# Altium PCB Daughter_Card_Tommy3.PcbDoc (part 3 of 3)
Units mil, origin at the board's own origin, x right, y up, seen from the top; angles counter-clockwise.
Board outline 2032.68 x 3237.01 mil, 8 copper layers (Top Layer, GND, AUX Routing (LVDS), 2.5V, AUX Route Vert, AUX Route Horz, GND (Plane2), Bottom Layer), stack 61.2 mil thick; 218 components, 194 nets, 1097 pads, 500 vias.
Unrouted connection lines stored in the file: 161.
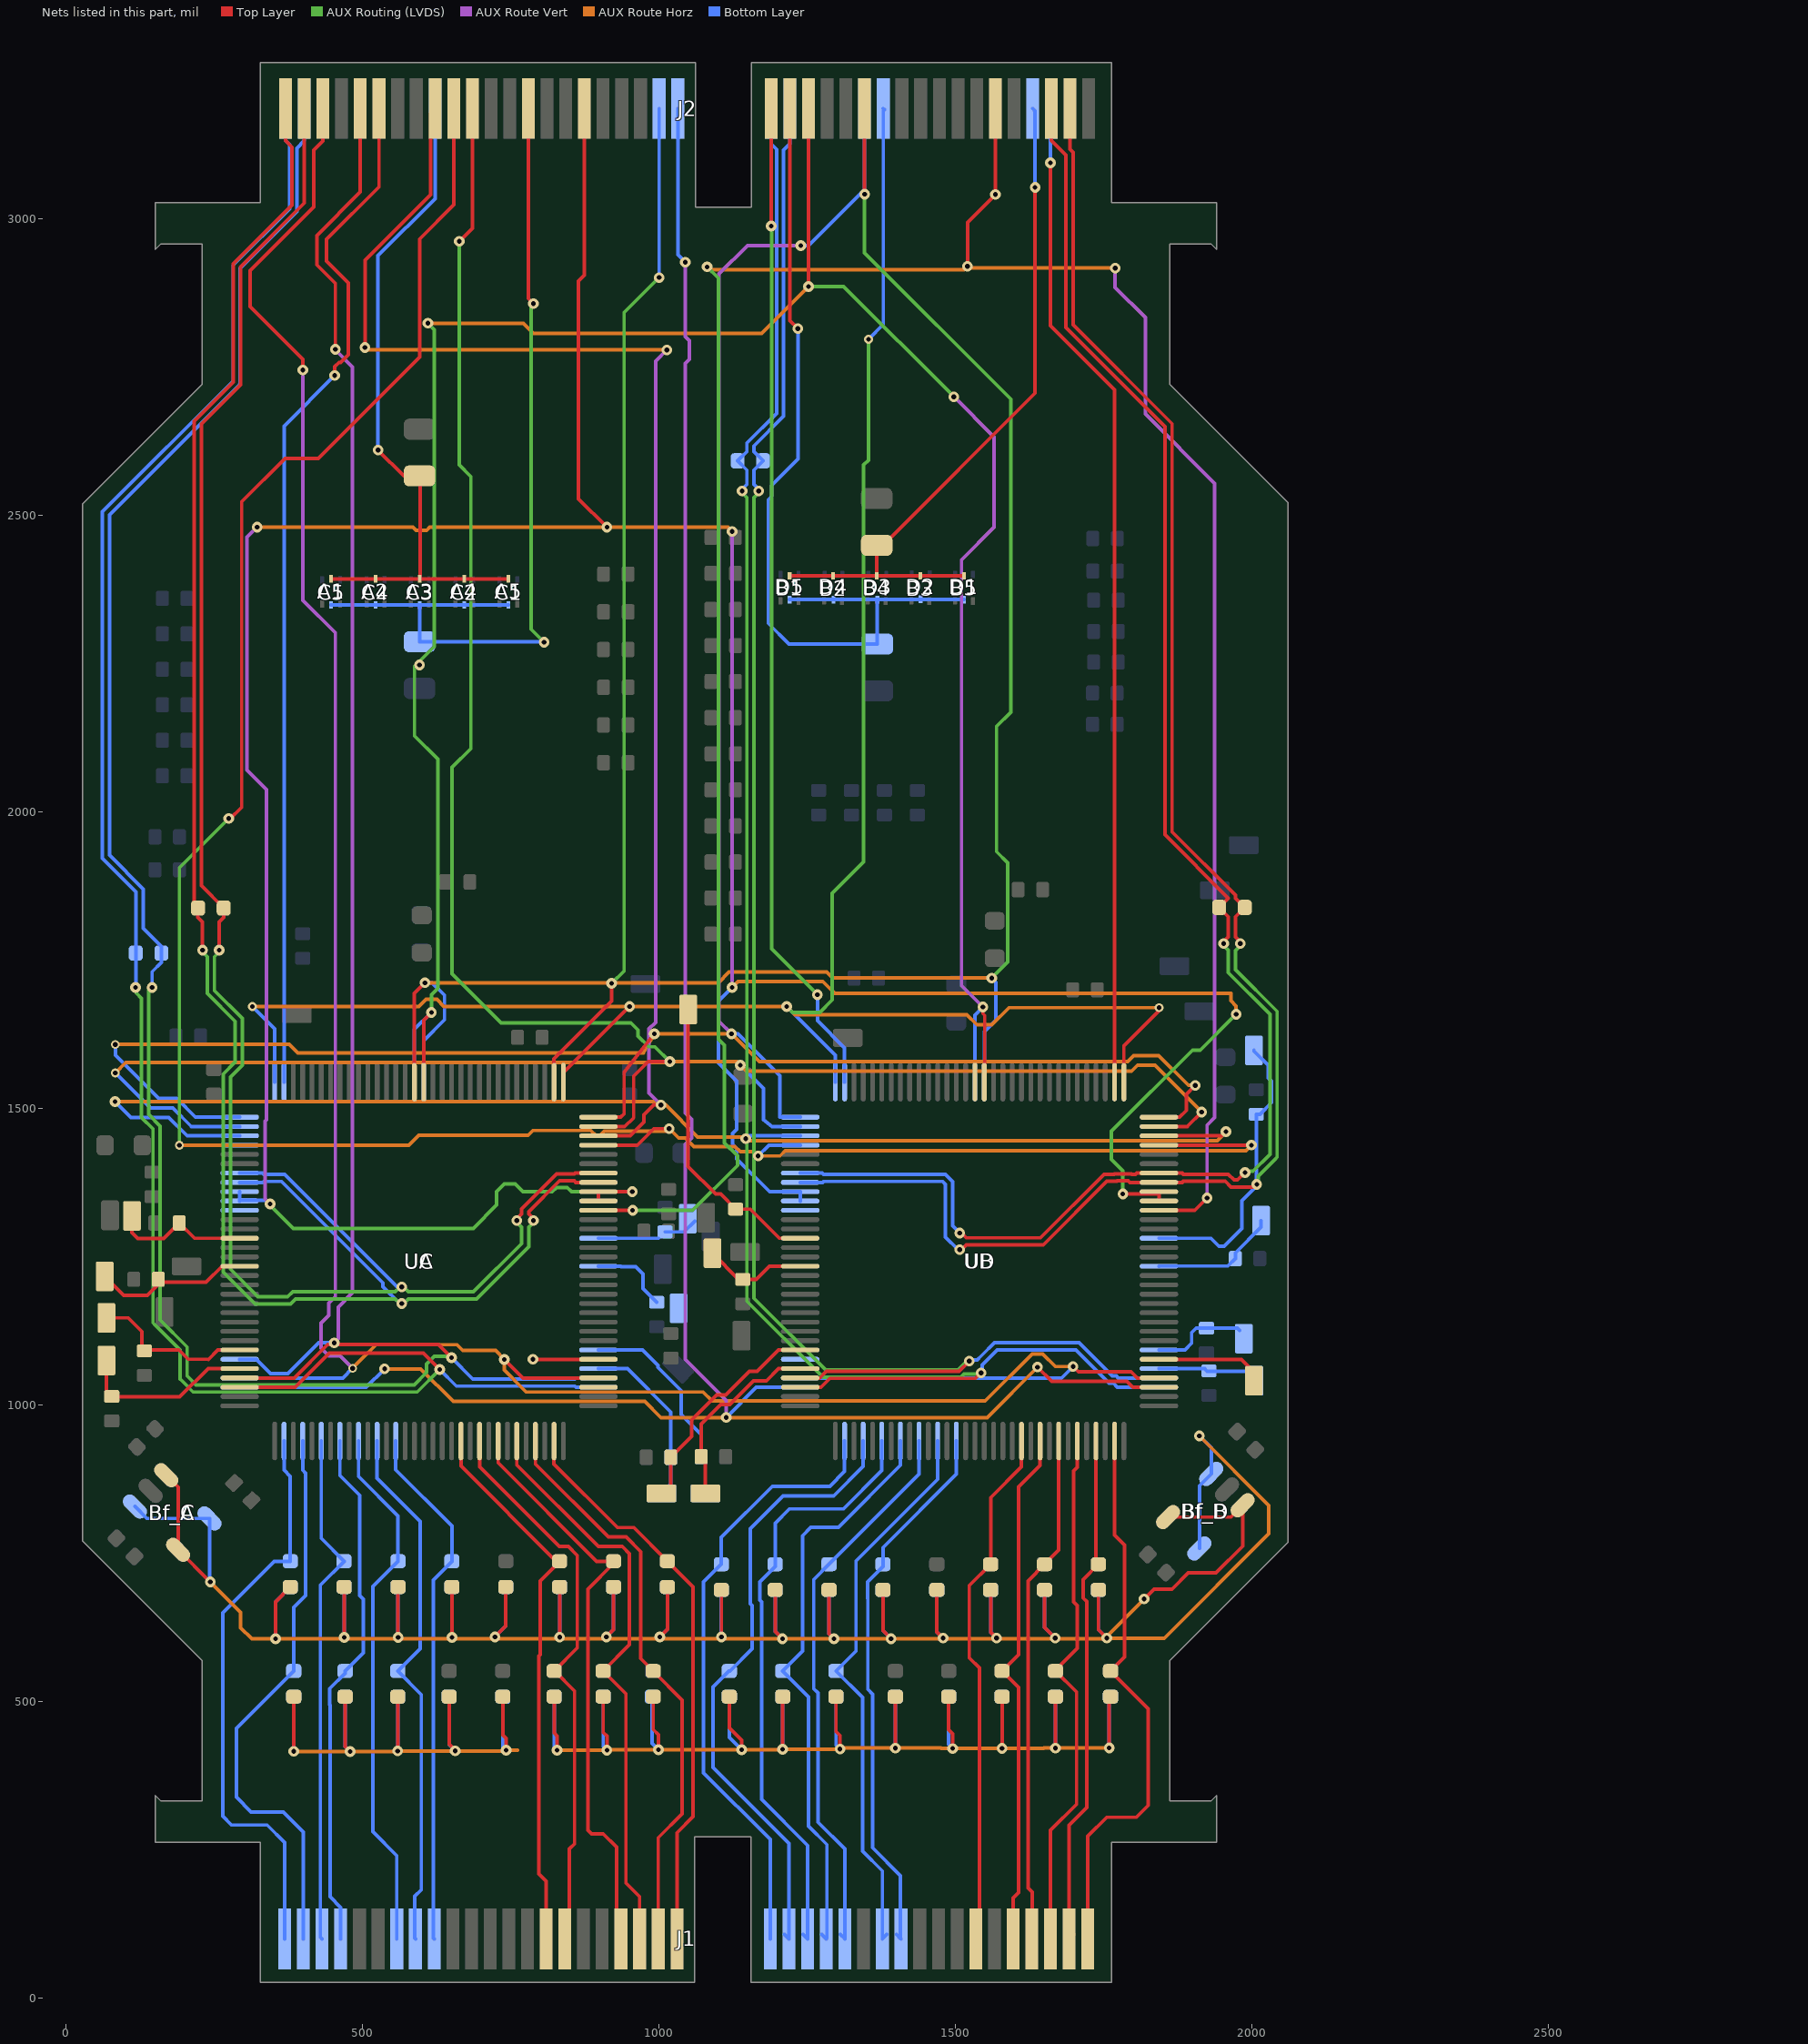
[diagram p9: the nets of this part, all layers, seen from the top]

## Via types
v1: diameter 18, hole 8, Top Layer to Bottom Layer, 106 vias
v2: diameter 18, hole 8, Top Layer to AUX Route Horz, 56 vias
v3: diameter 15, hole 8, Top Layer to Bottom Layer, 53 vias
v4: diameter 18, hole 8, AUX Route Vert to Bottom Layer, 42 vias
v5: diameter 18, hole 8, AUX Route Horz to Bottom Layer, 40 vias
v6: diameter 18, hole 8, Top Layer to AUX Route Vert, 34 vias
v7: diameter 18, hole 8, Top Layer to GND, 33 vias
v8: diameter 18, hole 8, GND (Plane2) to Bottom Layer, 27 vias
v9: diameter 18, hole 8, AUX Routing (LVDS) to Bottom Layer, 23 vias
v10: diameter 18, hole 8, Top Layer to AUX Routing (LVDS), 22 vias
v11: diameter 15, hole 8, Top Layer to 2.5V, 13 vias
v12: diameter 18, hole 8, Top Layer to 2.5V, 13 vias
v13: diameter 15, hole 8, Top Layer to GND, 10 vias
v14: diameter 18, hole 8, 2.5V to Bottom Layer, 8 vias
v15: diameter 15, hole 8, GND (Plane2) to Bottom Layer, 4 vias
v16: diameter 15, hole 8, Top Layer to AUX Route Horz, 4 vias
v17: diameter 18, hole 8, AUX Route Vert to AUX Route Horz, 4 vias
v18: diameter 15, hole 8, 2.5V to Bottom Layer, 2 vias
v19: diameter 18, hole 8, AUX Routing (LVDS) to AUX Route Vert, 2 vias
v20: diameter 15 (per signal layer), hole 8, Top Layer to GND, 1 vias
v21: diameter 15, hole 8, AUX Routing (LVDS) to Bottom Layer, 1 vias
v22: diameter 15, hole 8, Top Layer to AUX Route Vert, 1 vias
v23: diameter 8, hole 8, Top Layer to AUX Route Horz, 1 vias

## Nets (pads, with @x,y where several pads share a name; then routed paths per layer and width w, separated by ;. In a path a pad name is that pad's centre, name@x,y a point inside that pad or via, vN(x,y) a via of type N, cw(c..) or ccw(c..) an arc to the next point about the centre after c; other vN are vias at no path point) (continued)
RFin_10_C: J1.18 R10C.2 UC.19 | length 892.4
  Bottom Layer w6: UC.19@555.87,939.47 555.87,890.87 650.53,796.21 R10C.2@650.53,736.65 619,705.13 619,101.55 J1.18@620.55,100
RFin_10_D: J1.60 R10D.2 UD.19 | length 934.3
  Bottom Layer w6: J1.60@1400.28,107.67 J1.60@1407,100.95 ; J1.60@1407.95,100 J1.60@1407,100.95 ; UD.19@1501.18,939.47 1501.18,883.55 1377.39,759.77 R10D.2@1377.39,731.65 1377.39,727.88 1351.6,702.08 1351.6,674.21 1352,673.81 1352,520.63 1360,512.63 1360,253.63 1407,206.63 J1.60@1407,100.95
RFin_11_A: J1.29 R11A.2 UA.21 | length 925.6
  Top Layer w6: UA.21@665.77,939.47 665.77,897.23 R11A.2@826.35,736.65 ; J1.29@809.53,100 809.53,197.47 797.2,209.8 797.2,577.2 799.18,579.18 799.18,703.59 R11A.2@832.24,736.65
RFin_11_B: J1.67 R11B.2 UB.21 | length 896.4
  Top Layer w6: J1.67@1526.27,107.67 J1.67@1533.94,100 1540,106.06 1540,557 1523,574 1523,695.54 R11B.2@1559.11,731.65 1559.11,844.11 1611.08,896.08 UB.21@1611.08,939.47
RFin_11_C: J1.16 R11C.2 UC.21 | length 906.6
  Bottom Layer w6: UC.21@524.47,939.47 524.47,876.53 597,804 597,589.44 R11C.2@559.21,551.65 599,511.87 599,183 588,172 588,101.05 J1.16@589.05,100
RFin_11_D: J1.58 R11D.2 UD.21 | length 953.5
  Bottom Layer w6: J1.58@1384,107.54 J1.58@1376.46,100 1376.46,214.54 1343,248 1343,507 R11D.2@1298.35,551.65 1332,585.31 1332,737 1469.78,874.78 UD.21@1469.78,939.47
RFin_12_A: J1.31 R12A.2 UA.23 | length 954.1
  Top Layer w6: UA.23@697.17,939.47 697.17,896.17 831.87,761.46 846.96,761.46 862,746.43 862,590.66 R12A.2@822.99,551.65 823.69,551.65 857.35,518 857.35,260.09 848.69,251.43 848.69,107.67 J1.31@841.02,100
RFin_12_B: J1.71 R12B.2 UB.23 | length 891.4
  Top Layer w6: J1.71@1604.14,107.21 1596.93,100 1596.93,168.93 1606,178 1606,524 R12B.2@1578.35,551.65 1606,579.31 1606,862 1642.48,898.48 UB.23@1642.48,939.47
RFin_12_C: J1.14 R12C.2 UC.23 | length 901.5
  Bottom Layer w6: UC.23@493.07,939.47 493.07,879.93 559.67,813.33 R12C.2@559.67,736.65 517,693.98 517,281 557.56,240.44 J1.14@557.56,100
RFin_12_D: J1.54 R12D.2 UD.23 | length 945.1
  Bottom Layer w6: J1.54@1305.79,107.67 J1.54@1313,100.46 ; J1.54@1313.46,100 J1.54@1313,100.46 ; UD.23@1438.38,939.47 1438.38,883.5 R12D.2@1286.53,731.65 1260.74,705.86 1260.74,521.89 1268,514.63 1268,296.63 1313,251.63 J1.54@1313,100.46
RFin_13_A: J1.37 R13A.2 UA.25 | length 978.8
  Top Layer w6: UA.25@728.57,939.47 728.57,902.49 894.4,736.65 R13A.2@923.1,736.65 923.1,732.88 879.87,689.65 879.87,283.13 886,277 905.74,277 928,254.74 J1.37@928,107.51
RFin_13_B: J1.73 R13B.2 UB.25 | length 861.3
  Top Layer w6: J1.73@1625.03,103.39 J1.73@1628.44,100 ; J1.73@1629,107.36 1629,179 1622,186 1622,703.69 R13B.2@1649.97,731.65 1673.88,755.56 UB.25@1673.88,939.47
RFin_13_C: J1.8 R13C.2 UC.25 | length 886.7
  Bottom Layer w6: UC.25@461.67,939.47 461.67,881.33 495,848 495,679 501,673 501,582.18 R13C.2@470.47,551.65 470.47,547.88 444.68,522.08 444.68,494.61 445,494.29 445,171 463.07,152.93 J1.8@463.07,100
RFin_13_D: J1.52 R13D.2 UD.25 | length 991.1
  Bottom Layer w6: J1.52@1274.3,107.67 J1.52@1281.97,100 1283,101.03 1283,259 1252,290 1252,508 R13D.2@1208.35,551.65 1241.69,585 1241.69,779.69 1256,794 1302.44,794 1406.98,898.54 UD.25@1406.98,939.47
RFin_14_A: J1.39 R14A.2 UA.27 | length 996.4
  Top Layer w6: UA.27@759.97,939.47 759.97,898.97 897.47,761.46 937.82,761.46 950,749.29 950,595.98 R14A.2@905.67,551.65 944,513.32 944,194 967.01,170.99 J1.39@967.01,100 J1.39@959.34,107.67
RFin_14_B: J1.75 R14B.2 UB.27 | length 892.3
  Top Layer w6: J1.75@1659.92,100 1659.92,282.92 1704,327 1704,516 R14B.2@1668.35,551.65 1668.35,553.35 1705,590 1705,662.01 1699.03,667.98 1699.03,889.03 1705,895 ; 1705.28,895.28 UB.27@1705.28,939.47
RFin_14_C: J1.6 R14C.2 UC.27 | length 873.3
  Bottom Layer w6: UC.27@430.27,939.47 430.27,775.2 R14C.2@468.81,736.65 428.68,696.52 428.68,102.9 J1.6@431.57,100
RFin_14_D: J1.50 R14D.2 UD.27 | length 1022.1
  Bottom Layer w6: J1.50@1242.8,107.67 J1.50@1250.47,100 1250.47,257.53 1173,335 1173,668.37 1169.88,671.49 1169.88,702.08 1195.68,727.88 R14D.2@1195.68,731.65 1195.68,800.68 1220,825 1310.81,825 1375.58,889.77 UD.27@1375.58,939.47
RFin_15_A: J1.41 R15A.2 UA.29 | length 987.2
  Top Layer w6: UA.29@791.37,939.47 791.37,900.63 914.54,777.46 944.45,777.46 969,752.91 969,572.65 R15A.2@990,551.65 1039,502.65 1039,311 998.5,270.5 J1.41@998.5,100 J1.41@1006.17,107.67
RFin_15_B: J1.77 R15B.2 UB.29 | length 877.4
  Top Layer w6: J1.77@1699.09,107.67 1691.42,100 1691.42,291.79 1721,321.37 1721,668.64 1715.03,674.61 1715.03,705.86 R15B.2@1740.83,731.65 1736.68,735.8 UB.29@1736.68,939.47
RFin_15_C: J1.4 R15C.2 UC.29 | length 968.3
  Bottom Layer w6: UC.29@398.87,939.47 398.87,890.13 403.75,885.25 403.75,678.75 383.86,658.86 R15C.2@383.86,551.65 287,454.8 287,339 312,314 366,314 400.08,279.92 J1.4@400.08,100
RFin_15_D: J1.48 R15D.2 UD.29 | length 1060.7
  Bottom Layer w6: J1.48@1211.31,107.67 1218.98,100 1218.98,261.02 1091,389 1091,525 1117.65,551.65 R15D.2@1118.35,551.65 1119.65,551.65 1157,589 1157,661.75 1153.88,664.86 1153.88,791.88 1209,847 1294.4,847 1344.18,896.77 ; 1344.18,898 UD.29@1344.18,939.47
RFin_16_A: J1.43 R16A.2 UA.31 | length 966.4
  Top Layer w6: UA.31@822.77,939.47 822.77,900.23 929.54,793.46 957.15,793.46 R16A.2@1013.96,736.65 1057,693.61 1057,306 1030,279 J1.43@1030,100 J1.43@1031.8,101.8
RFin_16_B: J1.79 R16B.2 UB.31 | length 965.4
  Top Layer w6: J1.79@1730.74,107.83 J1.79@1722.9,100 1722.91,272.91 1755,305 1805,305 1825,325 1825,487.88 R16B.2@1761.23,551.65 1785,575.43 1785,764 1768.08,780.92 UB.31@1768.08,939.47
RFin_16_C: J1.2 R16C.2 UC.31 | length 985.5
  Bottom Layer w6: UC.31@367.47,939.47 367.47,890.53 377.95,880.05 R16C.2@377.95,736.65 350.65,736.65 264,650 264,307 279,292 339,292 368.58,262.42 J1.2@368.58,100
RFin_16_D: J1.46 R16D.2 UD.31 | length 1041.2
  Bottom Layer w6: J1.46@1187.48,100 1187.48,267.52 1075,380 1075,701.84 R16D.2@1104.82,731.65 1104.82,776.82 1191,863 1287.78,863 1312.78,888 UD.31@1312.78,939.47
SCLK: J2.6 UA.36 UB.36 UC.36 UD.36 | length 4590.1
  Top Layer w6: v6(399,2745) 399,2763 310,2852 310,2912.37 417.6,3019.97 417.6,3115.6 433.09,3131.09 J2.6@433.09,3186 ; v2(739,1077) 770.28,1045.72 UA.36@897.62,1045.72 ; v1(1698,1065) 1707,1056 1796,1056 1806.28,1045.72 UB.36@1842.93,1045.72
  AUX Route Vert w6: v6(399,2745) 399,2357 454,2302 454,1182.99 442.75,1171.74 442.75,1151.12 430,1138.37 430,1095.89 442.89,1083 462,1083 v3(483,1062)
  AUX Route Horz w6: v3(483,1062) 522.8,1101.8 658.91,1101.8 668.71,1092 724,1092 v2(739,1077) 739,1059 776,1022 1074.11,1022 1089.11,1007 1549.89,1007 1628.89,1086 1647.11,1086 1668.11,1065 v1(1698,1065)
  Bottom Layer w6: UC.36@292.62,1045.72 466.72,1045.72 v3(483,1062) ; UD.36@1237.93,1045.72 1678.72,1045.72 v1(1698,1065)
SHoutA: UA.38 | length 110.5
  Top Layer w6: v2(787.12,1077.12) UA.38@897.62,1077.12
SHoutB: SHoutB.1 UB.38 | length 183.8
  Top Layer w6: UB.38@1842.93,1077.12 1981.88,1077.12 2003,1056 SHoutB.1@2003,1041
SHoutC: J2.10 UC.38 | length 2339.9
  Top Layer w6: v6(454,2780) 454,2891.26 423,2922.26 423,2972 496.09,3045.09 J2.10@496.09,3186
  AUX Route Vert w6: v4(452,1105) 458.75,1111.75 458.75,1165.11 483,1189.36 483,2750 454,2779 v6(454,2780)
  Bottom Layer w6: UC.38@292.62,1077.12 320.88,1077.12 345,1053 374,1053 426,1105 v4(452,1105)
SHoutD: UD.38
SIN: J2.43 UA.35 UB.35 UC.35 UD.35 | length 4048.1
  Top Layer w6: v1(1638,1064) 1662,1040 1789,1040 1798.98,1030.02 UB.35@1842.93,1030.02
  AUX Route Vert w6: v4(1044,2927) 1044,2801.74 1051,2794.74 1051,2763.26 1044,2756.26 1044,1492.74 1055,1481.74 1055,1450.26 1044,1439.26 1044,1077 1113,1008 v1(1113,979)
  AUX Route Horz w6: v5(537,1061) 597.89,1061 652.89,1006 976.11,1006 1003.11,979 v1(1113,979) 1553,979 v1(1638,1064)
  Bottom Layer w6: UC.35@292.62,1030.02 506.02,1030.02 v5(537,1061) ; J2.43@1031.52,3186 1031.52,2939.48 v4(1044,2927) ; v1(1113,979) 1164.02,1030.02 UD.35@1237.93,1030.02
SmplSel_AnyD: J2.46 UD.66 | length 1691.4
  Top Layer w6: v6(1189,2988) J2.46@1189,3186
  AUX Routing (LVDS) w6: v6@1190,2987 1190,1769 v9(1267,1692)
  Bottom Layer w6: v9(1267,1692) 1267,1648 1312.78,1602.22 UD.66@1312.78,1544.47
SmplSel_S1: J2.57 UA.65 UB.65 UC.65 UD.65 | length 3821.8
  Top Layer w6: UA.65@838.47,1544.47 838.47,1560.47 v6(950,1672) ; UB.65@1783.78,1544.47 1783.78,1605.78 ; 1784.08,1606.08 1843,1665 v3(1843,1670)
  AUX Routing (LVDS) w6: v5(1215.15,1672) 1225.15,1662 1271,1662 1292,1683 1292,1863 1345,1916 1345,2585.11 1353,2593.11 v3(1353,2797)
  AUX Route Horz w6: v3(314,1672) 594.89,1672 606.89,1684 625.11,1684 637.11,1672 v6(950,1672) v5(1215.15,1672) 1229.15,1658 1519,1658 1536,1641 1561,1641 1590,1670 v3(1843,1670)
  Bottom Layer w6: v3(314,1672) 351.77,1634.23 UC.65@351.77,1544.47 ; v5(1215.15,1672) 1297.08,1590.08 UD.65@1297.08,1544.47 ; v3(1353,2797) 1378,2822 1378,3181.98 1380,3183.98 J2.57@1377.98,3186
  other v17: 950,1672
SmplSel_S2: J2.55 UA.64 UB.64 UC.64 UD.64 | length 4403.4
  Top Layer w6: UA.64@897.62,1485.32 935.32,1485.32 941,1491 941,1561 v2(992,1626) ; UB.64@1842.93,1485.32 1877.68,1485.32 1889,1496.64 1889,1524 v2(1904,1539)
  AUX Route Vert w6: v1(1122,1626) 1101,1647 1101,2907 1149,2955 v4(1239,2955)
  AUX Route Horz w6: v3(83,1608) 376.01,1608 390.51,1593.5 973.5,1593.5 v2(992,1626) v1@1121,1626 ; v1(1122,1626) 1169,1579 1790.11,1579 1800.11,1589 1842.63,1589 1892.63,1539 v2(1904,1539)
  Bottom Layer w6: v3(83,1608) 83,1590 156,1517 186.46,1517 217.85,1485.62 ; 218.15,1485.32 UC.64@292.62,1485.32 ; v1(1122,1626) 1133,1626 1203.68,1555.32 1203.68,1485.32 UD.64@1237.93,1485.32 ; v4(1239,2955) 1252,2955 1346.48,3049.48 J2.55@1346.48,3186
SmplSel_S3: J2.22 UA.63 UB.63 UC.63 UD.63 | length 4515.7
  Top Layer w6: v1(663,2962) 685.06,2984.06 J2.22@685.06,3186 ; UA.63@897.62,1469.62 941.65,1469.62 957,1484.37 957,1554.37 981.63,1579 v2(1018,1579) ; UB.63@1842.93,1469.62 1890.62,1469.62 ; 1890.92,1469.92 v2(1915,1494)
  AUX Routing (LVDS) w6: v1(663,2962) 663,2584.99 682.5,2565.49 682.5,2106.61 651,2075.11 651,1727 733.5,1644.5 952.49,1644.5 964.5,1632.49 964.5,1622.39 982.89,1604 993,1604 v2(1018,1579)
  AUX Route Horz w6: v3(83,1560) 100.5,1577.5 1016.5,1577.5 v2(1018,1579) 1131,1579 v5(1137,1573) 1147,1563 1796.74,1563 1806.74,1573 1836,1573 v2(1915,1494)
  Bottom Layer w6: v3(83,1560) 142,1501 179.84,1501 210.92,1469.92 ; 211.22,1469.62 UC.63@292.62,1469.62 ; v5(1137,1573) 1176,1534 1176,1481 1190.62,1469.62 UD.63@1237.93,1469.62
SmplSel_S4: J2.18 UA.62 UB.62 UC.62 UD.62 | length 4742.3
  Top Layer w6: v1(504,2783) 504,2930.37 614.4,3040.77 614.4,3178.33 J2.18@622.07,3186 ; UA.62@897.62,1453.92 951.37,1453.92 974.55,1477.1 974.55,1489.55 991,1506 v1(1003,1506) ; UB.62@1842.93,1453.92 1948.92,1453.92 ; 1949.22,1454.22 v2(1956,1461)
  AUX Route Vert w6: v1(1003,1506) 983,1526 983,1634.11 994,1645.11 994,2760 v17(1013,2779)
  AUX Route Horz w6: v5(82.5,1511.5) 997.5,1511.5 v1(1003,1506) 1011,1506 1065,1452 1143,1452 v5(1146,1449) ; v1(504,2783) 508,2779 v17(1013,2779) ; v5@1148,1451 1153,1446 1941,1446 v2(1956,1461) v2@1956,1458
  Bottom Layer w6: v5(82.5,1511.5) 109,1485 173.21,1485 203.99,1454.22 ; 204.29,1453.92 UC.62@292.62,1453.92 ; v5(1146,1449) 1150.92,1453.92 UD.62@1237.93,1453.92
SmplSel_S5: J2.20 UA.61 UB.61 UC.61 UD.61 | length 4295.5
  Top Layer w6: v1(274,1989) 274,1988 275,1987 296,2008 296,2523 369,2596 425,2596 596,2767 596,2966 653.57,3023.57 J2.20@653.57,3186 ; UA.61@897.62,1438.22 963.22,1438.22 991,1466 v2(1017,1466) ; UB.61@1842.93,1438.22 v2(1998.78,1438.22)
  AUX Routing (LVDS) w6: v21(191,1438.22) 191,1906 v1(274,1989)
  AUX Route Horz w6: v21(191,1438.22) 578.1,1438.22 594.89,1455 779.12,1455 787.12,1463 884.88,1463 892.88,1455 900.86,1455 907.58,1461.72 1012.72,1461.72 v2(1017,1466) 1033,1450 1044.37,1450 1058.37,1436 1127.89,1436 1136.89,1427 1160,1427 v5(1167,1420) 1204,1420 1213,1429 1235,1429 1989.56,1429 v2(1998.78,1438.22)
  Bottom Layer w6: v21(191,1438.22) UC.61@292.62,1438.22 ; v5(1167,1420) 1185.22,1438.22 UD.61@1237.93,1438.22
SmplSl_AnyA: J2.41 UA.66 | length 1715
  Top Layer w6: UA.66@822.77,1544.47 822.77,1584 920,1681.23 v10(920,1711)
  AUX Routing (LVDS) w6: v10(920,1711) 941,1732 941,2841.95 v9(1000.02,2900.98)
  Bottom Layer w6: v9(1000.02,2900.98) J2.41@1000.02,3186
SmplSl_AnyB: J2.75 UB.66 | length 1689.1
  Top Layer w6: v1@1661.51,3096 v1(1660,3094.49) 1660,2820 1768.08,2711.92 UB.66@1768.08,1544.47
  Bottom Layer w6: v1(1660,3094.49) 1660,3184.49 J2.75@1661.51,3186
SmplSl_AnyC: J2.12 UC.66 | length 1740.3
  Top Layer w6: v1(453,2736) 453,2750.89 460.11,2758 463.11,2758 476,2770.89 476,2891.89 439,2928.89 439,2965.37 527.58,3053.96 J2.12@527.58,3186
  Bottom Layer w6: UC.66@367.47,1544.47 367.47,2650.47 v1(453,2736)
SR_Clock: J2.50 UA.80 UB.80 UC.80 UD.80 | length 4112.6
  Top Layer w6: UA.80@602.97,1544.47 602.97,1648.97 v1(616,1662) ; v1(1252,2886) J2.50@1251.99,3186 ; v1(1546,1671) 1546,1660 1549,1657 1549,1545.19 UB.80@1548.28,1544.47
  AUX Route Vert w6: v1(1497,2700) 1565,2632 1565,2480 1510,2425 1510,1707 v1(1546,1671)
  AUX Routing (LVDS) w6: v9(610,2824) 621,2813 621,2278.89 587.5,2245.39 587.5,2128.39 627,2088.89 627,1702.89 616,1691.89 v1(616,1662) ; v1(1252,2886) 1311,2886 v1(1497,2700)
  AUX Route Horz w6: v9(610,2824) 770.89,2824 787.89,2807 1173,2807 v1(1252,2886)
  Bottom Layer w6: UC.80@587.27,1544.47 587.27,1633.27 v1(616,1662) ; UD.80@1532.58,1544.47 1532.58,1657.58 v1(1546,1671)
SR_Sel: J2.56 UA.81 UB.81 UC.81 UD.81 | length 3128.8
  Top Layer w6: UA.81@587.27,1544.47 587.27,1694.27 v1(605,1712) ; v6(1346.48,3041.48) J2.56@1346.48,3186
  AUX Routing (LVDS) w6: v6(1346.48,3041.48) 1346.48,2942.52 1593,2696 1593,2168.11 1569,2144.11 1569,1933 1588,1914 1588,1747 v9(1561,1720)
  AUX Route Horz w6: v1(605,1712) 1099.89,1712 1117.89,1730 1282.74,1730 1292.74,1720 v9(1561,1720)
  Bottom Layer w6: UC.81@602.97,1544.47 602.97,1614.6 638,1649.63 638,1691 617,1712 v1(605,1712) ; UD.81@1548.28,1544.47 1548.58,1581.79 1548.58,1629.58 1568,1649 1568,1713 v9(1561,1720)
TRG_A: A1.3 A2.3 A3.3 A4.3 A5.3 J2.17 R_Trig_A.1 | length 1174.9
  Top Layer w6: A1.3@447,2393 A2.3@521.75,2393 A3.3@596.5,2393 A5.3@746,2393 ; v1(526,2610) 569.37,2566.63 R_Trig_A.1@596,2566.63 ; A3.3@597,2393.5 R_Trig_A.1@597,2565.63
  Bottom Layer w6: v1(526,2610) 526,2938 622.07,3034.07 J2.17@622.07,3186
TRG_B: B1.3 B2.3 B3.3 B4.3 B5.3 J2.73 R_Trig_B.1 | length 1200.5
  Top Layer w6: B1.3@1220,2398 B2.3@1293.5,2398 B4.3@1367,2398 ; B5.3@1514,2398 B3.3@1440.5,2398 B4.3@1367,2398 ; v1(1634,3053) 1634,2706 1377.63,2449.63 R_Trig_B.1@1367,2449.63 B4.3@1367,2398
  Bottom Layer w6: J2.73@1629.96,3186 1634,3181.96 v1(1634,3053)
TRG_C: C1.3 C2.3 C3.3 C4.3 C5.3 J2.28 R_Trig_C.1 | length 1484.5
  Top Layer w6: J2.28@779.55,3186 779.55,2865.45 v2(788,2857)
  AUX Routing (LVDS) w6: v2(788,2857) 784,2853 784,2308 v9(806,2286)
  Bottom Layer w6: C5.3@447,2349 C1.3@745.83,2349 ; C3.3@596,2348 R_Trig_C.1@596,2287 805,2287 v9(806,2286)
  other v5: 596,2248
TRG_D: D1.3 D2.3 D3.3 D4.3 D5.3 J2.48 R_Trig_D.1 | length 1461.8
  Top Layer w6: J2.48@1220.5,3186 1220.5,2828.5 v1(1234,2815)
  Bottom Layer w6: D5.3@1220,2358 D4.3@1294,2358 D3.3@1368,2358 ; v1(1234,2815) 1234,2595 1190,2551 1190,2531.89 1184,2525.89 1184,2318 1219,2283 R_Trig_D.1@1368,2283 D3.3@1368,2358 ; D1.3@1514,2358 D3.3@1368,2358
TX_AC_SSTin_N: J2.1 RsstC.1 UA.126 UC.126 | length 3460.2
  Top Layer w6: UA.126@292.62,1030.02 385.99,1030.02 443.49,1087.51 602.49,1087.51 v10(630,1060)
  AUX Routing (LVDS) w6: v9(117,1704) 118.51,1702.49 118.51,1694.51 127,1686.03 127,1485.04 146.49,1465.55 146.49,1138.51 150,1135 192,1093 192,1044.03 195.51,1040.51 214.03,1022 592,1022 v10(630,1060)
  Bottom Layer w6: v9(117,1704) 118,1705 118,1745.55 ; RsstC.1@117.35,1762 117.35,1746.2 118,1745.55 ; J2.1@370.1,3186 370.1,3131.82 377,3124.92 377,3017 281.51,2921.51 281.51,2726.49 61,2505.97 61,1922 118,1865 118,1745.55 ; v10(630,1060) 658,1032 858,1032 ; 859.98,1030.02 UC.126@897.62,1030.02
  other v9: 630,1060
TX_AC_SSTin_P: J2.3 RsstC.2 UA.125 UC.125 | length 3479.9
  Top Layer w6: UA.125@292.62,1045.72 384.72,1045.72 441,1102 627.6,1102 v10(649.8,1079.8)
  AUX Routing (LVDS) w6: v9(145,1704) 144,1703 139,1703 139,1490.01 158.49,1470.52 158.49,1143.49 204,1097.97 204,1049 219,1034 587.03,1034 608,1054.97 608,1069.11 620.89,1082 647.6,1082 v10(649.8,1079.8)
  Bottom Layer w6: v9(145,1704) 145,1730.55 160.65,1746.2 RsstC.2@160.65,1762 160.65,1773.35 130,1804 130,1869.97 73,1926.97 73,2501 290,2718 293.51,2721.51 293.51,2916.54 385.49,3008.51 389,3012.03 389,3119.22 401.6,3131.82 J2.3@401.6,3186 ; v10(649.8,1079.8) 685.6,1044 858,1044 ; 859.72,1045.72 UC.125@897.62,1045.72
  other v9: 649.8,1079.8
TX_AC_WL_CLK_N: J2.2 RwA.1 UA.57 UC.57 | length 3218.6
  Top Layer w6: v10(230,1767) 230,1814.55 222.35,1822.2 RwA.1@222.35,1838 216,1844.35 216,2658.97 282,2724.97 282,2923.97 381,3022.97 381,3120.92 370.1,3131.82 J2.2@370.1,3186 ; v1(788,1311) 788,1314.11 780,1322.11 780,1326 832,1378 857,1378 ; 859.58,1375.42 UA.57@897.62,1375.42
  AUX Routing (LVDS) w6: v10(230,1767) 230,1763.89 238,1755.89 238,1694 285,1647 285,1578.08 265,1558.08 265,1224.03 268.51,1220.51 310.03,1179 318.53,1170.5 378.46,1170.5 386.96,1179 554.89,1179 562.89,1171 v9(566,1171) 569.11,1171 577.11,1179 691.97,1179 780,1267.03 780,1299.89 788,1307.89 v1(788,1311)
  Bottom Layer w6: UC.57@292.62,1375.42 331.42,1375.42 ; 333,1377 363.4,1377 534.4,1206 534.4,1199.49 562.89,1171 v9(566,1171)
TX_AC_WL_CLK_P: J2.4 RwA.2 UA.58 UC.58 | length 3201.2
  Top Layer w6: v10(258,1767) 258,1814.55 265.65,1822.2 RwA.2@265.65,1838 228,1875.65 228,2654 294,2720 294,2919 401.6,3026.6 J2.4@401.6,3186 ; v1(760,1311) 760,1314.11 768,1322.11 768,1330.97 827.03,1390 857,1390 ; 858.12,1391.12 UA.58@897.62,1391.12
  AUX Routing (LVDS) w6: v10(258,1767) 258,1763.89 250,1755.89 250,1698.97 297,1651.97 297,1573.11 277,1553.11 277,1229 323.5,1182.5 373.49,1182.5 381.99,1191 554.89,1191 562.89,1199 v9(566,1199) 569.11,1199 577.11,1191 687,1191 768,1272 768,1299.89 760,1307.89 v1(760,1311)
  Bottom Layer w6: UC.58@292.62,1391.12 330.88,1391.12 ; 333,1389 368.37,1389 558.37,1199 v9(566,1199)
TX_BD_SSTin_N: J2.45 RsstD.1 UB.126 UD.126 | length 3171.5
  Top Layer w6: UB.126@1237.93,1030.02 1273.02,1030.02 1288,1045 1533.6,1045 v1(1542.8,1054.2)
  AUX Routing (LVDS) w6: v9(1140,2541) 1140,2537.89 1148,2529.89 1148,1175.03 1272.51,1050.51 1276.03,1047 1508.97,1047 1512.49,1050.51 1513.97,1052 1540.6,1052 v1(1542.8,1054.2)
  Bottom Layer w6: v9(1140,2541) 1140,2544.11 1148,2552.11 1148,2576.35 RsstD.1@1132.35,2592 1148,2607.65 1148,2621.97 1198,2671.97 1198,3117 1189,3126 J2.45@1189,3186 ; v1(1542.8,1054.2) 1545,1056.4 1545,1067.72 1570.28,1093 1703,1093 1759,1037 1766.11,1037 1772.79,1030.32 1800,1030.32 ; 1797.98,1030.02 UD.126@1842.93,1030.02
TX_BD_SSTin_P: J2.47 RsstD.2 UB.125 UD.125 | length 3124.1
  Top Layer w6: UB.125@1237.93,1045.72 1270.72,1045.72 1282,1057 1506,1057 v1(1523,1074)
  AUX Routing (LVDS) w6: v9(1168,2541) 1168,2537.89 1160,2529.89 1160,1180 1281,1059 1504,1059 1519,1074 v1(1523,1074)
  Bottom Layer w6: v9(1168,2541) 1168,2544.11 1160,2552.11 1160,2576.35 RsstD.2@1175.65,2592 1160,2607.65 1160,2617 1210,2667 1210,3116 1220.5,3126.5 J2.47@1220.5,3186 ; v1(1523,1074) 1525.2,1076.2 1536.51,1076.2 1543.66,1083.34 1565.31,1105 1707.97,1105 1763.97,1049 1771.08,1049 1774.36,1045.72 UD.125@1842.93,1045.72
TX_BD_WL_CLK_N: J2.78 RwB.1 UB.57 UD.57 | length 2916.3
  Top Layer w6: v1(1507,1262) 1510.11,1262 1518.11,1270 1648,1270 1755.27,1377.27 1772.16,1377.27 1772.89,1378 1791.11,1378 1793.69,1375.42 UB.57@1842.93,1375.42 1882,1375.42 1883.85,1377.27 1954.73,1377.27 1964.51,1367.49 2003.08,1367.49 v10(2007.8,1372.2) ; J2.78@1692.94,3186 1692.94,3117.29 1698,3112.23 1698,2821.6 1865,2654.6 1865,1966.62 1972,1859.62 1972,1854.65 RwB.1@1987.65,1839 1972,1823.35 1972,1789.11 1980,1781.11 v10(1980,1778)
  AUX Routing (LVDS) w6: v10(1980,1778) 1980,1774 1972,1766 1972,1733.97 2042.16,1663.81 2042.16,1417.87 2038.64,1414.36 2010,1385.72 2010,1374.4 v10(2007.8,1372.2)
  Bottom Layer w6: UD.57@1237.93,1375.42 1275.42,1375.42 ; 1277,1377 1478,1377 1483,1372 1483,1282.89 1503.89,1262 v1(1507,1262)
TX_BD_WL_CLK_P: J2.76 RwB.2 UB.58 UD.58 | length 2882.4
  Top Layer w6: v1(1507,1290) 1510.11,1290 1518.11,1282 1643.03,1282 1750.3,1389.27 1767.19,1389.27 1767.92,1390 1796.08,1390 1796.81,1389.27 1803.27,1389.27 1805.12,1391.12 UB.58@1842.93,1391.12 1882,1391.12 1883.85,1389.27 1959.7,1389.27 1969.49,1379.49 1975.49,1379.49 v10(1988,1392) ; J2.76@1661.44,3186 1661.44,3131.82 1686,3107.26 1686,2816.63 1853,2649.63 1853,1961.65 1960,1854.65 RwB.2@1944.35,1839 1960,1823.35 1960,1789.11 1952,1781.11 v10(1952,1778)
  AUX Routing (LVDS) w6: v10(1952,1778) 1952,1774.89 1960,1766.89 1960,1729 2030.16,1658.84 2030.16,1422.84 2001.51,1394.2 1990.2,1394.2 v10(1988,1392)
  Bottom Layer w6: UD.58@1237.93,1391.12 1274.88,1391.12 ; 1277,1389 1482.97,1389 1495,1376.97 1495,1302 v1(1507,1290)
VadjN_A: CN_A.2 UA.122 VadjN_A.1 | length 292.1
  Top Layer w6: VadjN_A.1@76.67,1138.33 VadjN_A.1@68,1147 105,1147 128,1124 128,1091.67 129.15,1092.82 190.18,1092.82 205.58,1077.42 240,1077 255.82,1092.82 UA.122@292.62,1092.82
VadjNB: CN_B.2 UB.122 VadjNB.1 | length 354.5
  Top Layer w6: 1019.67,866.67 CN_B.2@1019.67,912 1055,947.33 1055,974.74 1097.26,1017 1112.37,1017 1152.37,1057 1165.27,1057 1201.08,1092.82 UB.122@1237.93,1092.82
VadjNC: CN_C.2 UC.122 VadjNC.1 | length 295
  Bottom Layer w6: UC.122@897.62,1092.82 971.82,1092.82 998,1066.63 998,1063.37 1037,1024.37 1037,984 1070.66,950.34 CN_C.2@1070.66,913
VadjND: CN_D.2 UD.122 VadjND.1 | length 163.3
  Bottom Layer w6: UD.122@1842.93,1092.82 1886.59,1092.82 1898,1104.23 1898,1122 1905.67,1129.67 CN_D.2@1923,1129.67 1975.33,1129.67 VadjND.1@1979,1126
VadjP_A: CP_A.2 UA.124 VadjP_A.1 | length 306.7
  Top Layer w6: VadjP_A.1@68,1075 CP_A.2@68,1013.67 ; CP_A.2@68.67,1013 CP_A.2@68,1013.67 ; UA.124@292.62,1061.42 239.42,1061.42 191.67,1013.67 CP_A.2@68,1013.67
VadjPB: CP_B.2 UB.124 VadjPB.1 | length 315.7
  Top Layer w6: CP_B.2@1071,913 1071,968.11 1103.89,1001 1119,1001 1159,1041 1181,1041 1201.42,1061.42 UB.124@1237.93,1061.42 ; VadjPB.1@1078,851 CP_B.2@1078,906
VadjPC: CP_C.2 UC.124 VadjPC.1 | length 296.1
  Bottom Layer w6: UC.124@897.62,1061.42 946.58,1061.42 1019.67,988.33 CP_C.2@1019.67,912 1019.67,866.67 VadjPC.1@1004,851
VadjPD: CP_D.2 UD.124 VadjPD.1 | length 156.9
  Bottom Layer w6: UD.124@1842.93,1061.42 1919.58,1061.42 1924,1057 VadjPD.1@1998,1057
Vdischarge_A: CDisA.2 UA.110 VdisA.1 | length 235.2
  Top Layer w6: VdisA.1@111,1319 111,1291 121,1281 164.67,1281 CDisA.2@190.67,1307 216.45,1281.22 UA.110@292.62,1281.22
Vdischarge_B: CDisB.2 UB.110 VdisB.1 | length 503.9
  Top Layer w6: VdisB.1@1049,1667 1049,1402.11 1095.44,1355.67 1103.66,1355.67 CDisB.2@1129,1330.33 1153.67,1330.33 1202.78,1281.22 UB.110@1237.93,1281.22
Vdischarge_C: CDisC.2 UC.110 VdisC.1 | length 159.1
  Bottom Layer w6: UC.110@897.62,1281.22 999.22,1281.22 ; CDisC.2@1010,1292 1042,1292 VdisC.1@1060,1310
Vdischarge_D: CDisD.2 UD.110 VdisD.1 | length 494.4
  Bottom Layer w6: UD.110@1842.93,1281.22 1930.78,1281.22 1944,1268 1952.56,1268 1982.56,1298 1982.56,1344.56 2007,1369 CDisD.2@2007,1490.33 2013.33,1490.33 2032.8,1509.8 2032.8,1545.98 2027,1551.77 2027,1573 2003,1597 VdisD.1@2003,1598
Vped1: Bf_A.1 Bf_A.4 Bf_B.1 Bf_B.4 Bf_C.1 Bf_C.4 Bf_D.1 Bf_D.4 R1A.1 R1B.1 R1C.1 R1D.1 R2A.1 R2B.1 R2C.1 R2D.1 R3A.1 R3B.1 R3C.1 R3D.1 R4A.1 R4B.1 R4C.1 R4D.1 R5A.1 R5B.1 R5C.1 R5D.1 R6A.1 R6B.1 R6C.1 R6D.1 R7A.1 R7B.1 R7C.1 R7D.1 R8A.1 R8B.1 R8C.1 R8D.1 R9A.1 R9B.1 R9C.1 R9D.1 R10A.1 R10B.1 R10C.1 R10D.1 R11A.1 R11B.1 R11C.1 R11D.1 R12A.1 R12B.1 R12C.1 R12D.1 R13A.1 R13B.1 R13C.1 R13D.1 R14A.1 R14B.1 R14C.1 R14D.1 R15A.1 R15B.1 R15C.1 R15D.1 R16A.1 R16B.1 R16C.1 R16D.1 | length 10308.9
  Top Layer w6: Bf_A.1@168.84,881.78 188.89,861.74 Bf_A.4@188.89,755.95 ; Bf_A.4@188.89,752.11 Bf_A.4@188.89,755.95 ; v2(243,701.84) Bf_A.4@188.89,755.95 ; v2(353,606) 353,668.39 R1A.1@377.95,693.35 ; v1(383.86,416.14) R2A.1@383.86,508.35 ; v2(468.81,608.19) R3A.1@468.81,693.35 ; R4A.1@470.47,508.35 470.47,424.53 v1(479,416) ; v1(559.21,416.79) R6A.1@559.21,508.35 ; v2(559.67,608.33) R5A.1@559.67,693.35 ; R8A.1@645.83,508.35 645.83,428.17 656,418 v1(656,417) ; v2(650.53,608.47) R7A.1@650.53,693.35 ; v2(723,609) 741.39,627.39 R9A.1@741.39,693.35 ; R10A.1@736.38,508.35 736.38,443.62 742,438 v1(742,418) ; R12A.1@822.99,508.35 822.99,447.01 828,442 v1(828,418) ; v2(832.24,608.76) R11A.1@832.24,693.35 ; R14A.1@905.67,508.35 905.67,448.33 912,442 v1(912,418) ; v2(911,609) 923.1,621.1 R13A.1@923.1,693.35 ; R15A.1@990,508.35 990,453 999,444 v1(999,419) ; v2(1001,609.08) 1013.96,622.04 R16A.1@1013.96,693.35 ; R1B.1@1104.82,688.35 1105,688.16 v2(1105,609) ; R2B.1@1118.35,508.35 1118.35,455.65 1139,435 v1(1139,419) ; R3B.1@1195.68,688.35 1195.68,618.32 v2(1208,606) ; v1(1208.35,419.65) R4B.1@1208.35,508.35 ; R5B.1@1286.53,688.35 1286.53,614.47 v2(1295,606) ; R6B.1@1298.35,508.35 1298.35,449.65 1305,443 v1(1305,420) ; R7B.1@1377.39,688.35 1377.39,619.61 v2(1391,606) ; v1(1398.35,421.65) R8B.1@1398.35,508.35 ; R9B.1@1468.25,688.35 1468.25,617.75 v2(1479,607) ; R10B.1@1488.35,508.35 1488.35,452.65 1495,446 v1(1495,421) ; R11B.1@1559.11,688.35 1559.11,616.89 v2(1569,607) ; v1(1578.35,421.35) R12B.1@1578.35,508.35 ; R13B.1@1649.97,688.35 1649.97,625.03 v2(1668,607) ; v1(1668.35,421.65) R14B.1@1668.35,508.35 ; R15B.1@1740.83,688.35 1740.83,621.17 v2(1755,607) ; v1(1759,422) 1759,506.12 R16B.1@1761.23,508.35 ; v2(1818,673) 1834.52,689.52 1865.04,689.52 1892.52,717 1939,717 1984.05,762.05 Bf_B.1@1984.05,831.16 1964.01,811.11 Bf_B.4@1858.22,811.11
  AUX Route Horz w6: v2(243,701.84) 294.42,650.42 294.42,624.58 313,606 v2(353,606) v2(1208,606) v2(1295,606) v2(1391,606) v5@1754,606 ; v1(383.86,416.14) v1@558.57,416.14 ; v1(559.21,416.79) 740.79,416.79 v1(742,418) 761.37,418 ; v1(828,418) v1(912,418) 913,419 v1(999,419) v1(1139,419) 1207.69,419 v1(1208.35,419.65) 1304.65,419.65 v1(1305,420) ; v1@1306.65,421.65 v1(1398.35,421.65) 1474.97,421.65 ; 1475.63,421 v1(1495,421) 1558.63,421 ; 1558.97,421.35 v1(1578.35,421.35) 1648.67,421.35 ; 1648.97,421.65 v1(1668.35,421.65) 1758.65,421.65 v1(1759,422) ; v2(1755,607) 1852,607 2028,783 2028,831 v5(1911,948) ; v5@1755,610 v2(1818,673)
  Bottom Layer w6: Bf_C.1@115.95,828.89 135.99,808.84 Bf_C.4@241.78,808.84 241.78,703.05 v2(243,701.84) ; v2(353,606) 353,668.39 R16C.1@377.95,693.35 ; v1(383.86,416.14) R15C.1@383.86,508.35 ; v2(468.81,608.19) R14C.1@468.81,693.35 ; R13C.1@470,507.87 R13C.1@470.47,508.35 470.47,424.53 ; v1(559.21,416.79) R11C.1@559.21,508.35 ; v2(559.67,608.33) R12C.1@559.67,693.35 ; v2(650.53,608.47) R10C.1@650.53,693.35 ; R9C.1@651,503.17 R9C.1@645.83,508.35 645.83,427.17 v1(656,417) ; v2(723,609) 741.39,627.39 R8C.1@741.39,693.35 ; v1(742,418) 736.38,423.62 R7C.1@736.38,508.35 R7C.1@745.24,499.48 ; R5C.1@822.99,508.35 822.99,423.01 v1(828,418) ; v2(832.24,608.76) R6C.1@832.24,693.35 ; R3C.1@905.67,508.35 905.67,424.33 v1(912,418) ; v2(911,609) 923.1,621.1 R4C.1@923.1,693.35 ; R1C.1@988.35,508.35 988.35,429.65 v1(999,419) ; v2(1001,609.08) 1013.96,622.04 R2C.1@1013.96,693.35 ; R16D.1@1104.82,688.35 1104.82,609.18 v2(1105,609) ; R15D.1@1118.35,508.35 1118.35,439.65 v1(1139,419) ; R14D.1@1195.68,688.35 1195.68,618.32 v2(1208,606) ; v1(1208.35,419.65) R13D.1@1208.35,508.35 ; R12D.1@1284,685.81 R12D.1@1286.53,688.35 1286.53,614.47 v2(1295,606) ; R11D.1@1298.35,508.35 1298.35,426.65 v1(1305,420) ; R10D.1@1377.39,688.35 1377.39,619.61 v2(1391,606) ; v1(1398.35,421.65) R9D.1@1398.35,508.35 ; R8D.1@1468.25,688.35 1468.25,617.75 v2(1479,607) ; 1488.35,427.65 R7D.1@1488.35,508.35 ; R6D.1@1559.11,688.35 1559.11,616.89 v2(1569,607) ; v1(1578.35,421.35) R5D.1@1578.35,508.35 ; R4D.1@1649.97,688.35 1649.97,625.03 v2(1668,607) ; v1(1668.35,421.65) R3D.1@1668.35,508.35 ; R2D.1@1740.83,688.35 1740.83,621.17 v2(1755,607) ; v1(1759,422) 1759,506.12 R1D.1@1761.23,508.35 ; v5(1911,948) 1931.16,927.84 Bf_D.1@1931.16,884.05 1911.11,864.01 Bf_D.4@1911.11,758.22
  other v5: 353,606 1208,606 1295,606 1391,606 1479,607 1569,607 1668,607 1755,607 468.81,608.19 559.67,608.33 650.53,608.47 723,609 832.24,608.76 911,609 1001,609.08 1105,609 243,701.84
VrampRef_A: Cr_A.2 UA.113 VrA.1 | length 273.1
  Top Layer w6: VrA.1@65.72,1217.72 VrA.1@65,1217 97,1185 137,1185 155.34,1203.34 Cr_A.2@155.34,1212 ; Cr_A.2@157,1207 236,1207 263.12,1234.12 UA.113@292.62,1234.12 ; Cr_A.2@161.67,1209.67 Cr_A.2@161.67,1215
VrampRef_B: Cr_B.2 UB.113 VrB.1 | length 193.5
  Top Layer w6: VrB.1@1090,1237.77 VrB.1@1090,1256 1134,1212 Cr_B.2@1141,1212 1164,1212 1186.12,1234.12 UB.113@1237.93,1234.12
VrampRef_C: Cramp_C.2 UC.113 VrampC.1 | length 137.6
  Bottom Layer w6: UC.113@897.62,1234.12 935.22,1234.12 ; 935.52,1233.82 935.82,1233.52 960.48,1233.52 973,1221 973,1196.34 Cramp_C.2@996,1173.34
VrampRef_D: Cramp_D.2 UD.113 VrampD.1 | length 215.9
  Bottom Layer w6: UD.113@1842.93,1234.12 1959.08,1234.42 Cramp_D.2@1971.66,1247 1971.66,1256.66 2015,1300 VrampD.1@2015,1311
WR_AddClr: J2.70 UA.54 UB.54 UC.54 UD.54 | length 4512.4
  Top Layer w6: UA.54@897.62,1328.32 v10(955.32,1328.32) ; v2(1520,2920) 1520,2994.09 v6(1566.95,3041.05) J2.70@1566.95,3186 ; UB.54@1842.93,1328.32 1903.32,1328.32 v6(1924,1349)
  AUX Route Vert w6: v1(1769,2917) 1769,2884.45 1820,2833.45 1820,2671 1937,2554 1937,1484.89 1924,1471.89 v6(1924,1349)
  AUX Routing (LVDS) w6: v10(955.32,1328.32) 1056.43,1328.32 1132,1403.89 1132,1420.11 1110.11,1442 1110,1442 1110,1606.89 1100,1616.89 1100,2900 v9(1081,2919)
  AUX Route Horz w6: v9(1081,2919) 1086,2914 1514,2914 v2@1519,2919 ; v2(1520,2920) 1523,2917 v1(1769,2917)
WR_ENA: J2.34 UA.55 UA.56 UB.55 UB.56 UC.55 UC.56 UD.55 UD.56 | length 6139.6
  Top Layer w6: J2.34@874.04,3186 874.04,2904.93 864,2894.89 864,2528 v2(912,2480) ; UA.55@897.62,1344.02 UA.56@897.62,1359.72 v10(954.72,1359.72) ; v1(1782,1356) 1839.21,1356 UB.56@1842.93,1359.72 UB.55@1842.93,1344.02
  AUX Route Vert w6: v1(322,2480) 305,2463 305,2070.45 338,2037.45 338,1481.11 335.62,1478.73 335.62,1347.38 v9(344,1339) ; v1(1123,1704) v4(1123,2473)
  AUX Routing (LVDS) w6: v9(344,1339) 344,1336.89 382.89,1298 686.74,1298 726,1337.26 726,1360.11 738.89,1373 757.11,1373 770.39,1359.72 819.61,1359.72 826.89,1367 845.11,1367 852.39,1359.72 v10(954.72,1359.72) ; v1(1782,1356) 1782,1395.01 1762.5,1414.51 1762.5,1461.49 1899.51,1598.5 1912.5,1598.5 v1(1973,1659)
  AUX Route Horz w6: v1(322,2480) 584.89,2480 589.89,2475 608.11,2475 613.11,2480 v2(912,2480) 1116,2480 v4(1123,2473) ; v1(1123,1704) 1133,1714 1276.11,1714 1296.11,1694 1964,1694 1964,1682 1973,1673 v1(1973,1659)
  Bottom Layer w6: UC.55@292.62,1344.02 UC.55@292.62,1345.32 ; UC.56@292.62,1359.72 UC.55@292.62,1345.32 ; v9(344,1339) 337.68,1345.32 UC.55@292.62,1345.32 ; v1(1123,1704) 1100,1681 1100,1577 1131,1546 1131,1465.11 1124,1458.11 1124,1439.89 1131,1432.89 1131,1415 1186.28,1359.72 UD.56@1237.93,1359.72 UD.55@1237.93,1344.02
pads on no net: J2.59 UA.43 UB.43 UC.43 UD.43
copper on no net:
  other v3: 1431,1086 1900,1301
  other v6: 1623,1351

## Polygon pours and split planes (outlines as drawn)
GND on Bottom Layer "BOTTOM_GND" (solid, pour order 25): 53,786 53,2509 253,2709 261,2701 1846,2701 2040,2507 2040,798 65,798
no net on Bottom Layer "Bottom" (solid, remove dead copper, pour order 15): 1061.02,3263.58 1061.02,3019.88 1155.51,3019.88 1155.51,3263.58 1762.8,3263.58 1762.8,3027.36 1939.96,3027.36 1939.96,2948.62 1931.3,2957.28 1861.22,2957.28 1861.22,2721.06 2060.24,2522.05 2060.24,768.11 1861.22,569.09 1861.22,332.87 1931.3,332.87 1939.96,341.54 1939.96,262.8 1762.8,262.8 1762.8,26.57 1154.53,26.57 1154.53,271.85 1060.04,271.85 1060.04,26.57 327.76,26.57 327.76,262.8 150.59,262.8 150.59,341.54 159.25,332.87 229.33,332.87 229.33,569.09 27.56,770.87 27.56,2519.29 229.33,2721.06 229.33,2957.28 159.25,2957.28 150.59,2948.62 150.59,3027.36 327.76,3027.36 327.76,3263.58
GND on Top Layer "Top Layer-GND" (solid, remove dead copper, pour order 40): 194,645 208,631 1892,631 1892,638 2038,784 2035,787 2035,2508 1833,2710 1837,2714 1837,2999 256,2999 257,3000 257,2699.97 67.03,2510 61,2510 61,793 48,780
GND on Top Layer "Top Layer" (solid, pour order 16): 1061.02,3263.58 1061.02,3019.88 1155.51,3019.88 1155.51,3263.58 1762.8,3263.58 1762.8,3027.36 1939.96,3027.36 1939.96,2948.62 1931.3,2957.28 1861.22,2957.28 1861.22,2721.06 2060.24,2522.05 2060.24,768.11 1861.22,569.09 1861.22,332.87 1931.3,332.87 1939.96,341.54 1939.96,262.8 1762.8,262.8 1762.8,26.57 1154.53,26.57 1154.53,271.85 1060.04,271.85 1060.04,26.57 327.76,26.57 327.76,262.8 150.59,262.8 150.59,341.54 159.25,332.87 229.33,332.87 229.33,569.09 27.56,770.87 27.56,2519.29 229.33,2721.06 229.33,2957.28 159.25,2957.28 150.59,2948.62 150.59,3027.36 327.76,3027.36 327.76,3263.58
GND on Top Layer "Top Layer-No Net 2" (solid, pour order 37): 2045,860 51,860 51,2495 43,2503 247,2707 1281,2707 1327,2753 1337,2743 1839,2743 1839,2715 2049,2505 2049,862
GND on Top Layer "Top Layer-No Net" (solid, pour order 31): 41,798 61,818 61,2510 260,2709 267,2702 1854,2702 1854,2692 2048,2498 2048,798
no net on Top Layer "Top Layer-No Net 1" (solid, pour order 27): 282,2152
no net on AUX Routing (LVDS) "AUX LVDS" (solid, pour order 12): 1061.02,3263.58 1061.02,3019.88 1155.51,3019.88 1155.51,3263.58 1762.8,3263.58 1762.8,3027.36 1939.96,3027.36 1939.96,2948.62 1931.3,2957.28 1861.22,2957.28 1861.22,2721.06 2060.24,2522.05 2060.24,768.11 1861.22,569.09 1861.22,332.87 1931.3,332.87 1939.96,341.54 1939.96,262.8 1762.8,262.8 1762.8,26.57 1154.53,26.57 1154.53,271.85 1060.04,271.85 1060.04,26.57 327.76,26.57 327.76,262.8 150.59,262.8 150.59,341.54 159.25,332.87 229.33,332.87 229.33,569.09 27.56,770.87 27.56,2519.29 229.33,2721.06 229.33,2957.28 159.25,2957.28 150.59,2948.62 150.59,3027.36 327.76,3027.36 327.76,3263.58
no net on AUX Route Vert "AUX Vert" (solid, pour order 13): 1061.02,3263.58 1061.02,3019.88 1155.51,3019.88 1155.51,3263.58 1762.8,3263.58 1762.8,3027.36 1939.96,3027.36 1939.96,2948.62 1931.3,2957.28 1861.22,2957.28 1861.22,2721.06 2060.24,2522.05 2060.24,768.11 1861.22,569.09 1861.22,332.87 1931.3,332.87 1939.96,341.54 1939.96,262.8 1762.8,262.8 1762.8,26.57 1154.53,26.57 1154.53,271.85 1060.04,271.85 1060.04,26.57 327.76,26.57 327.76,262.8 150.59,262.8 150.59,341.54 159.25,332.87 229.33,332.87 229.33,569.09 27.56,770.87 27.56,2519.29 229.33,2721.06 229.33,2957.28 159.25,2957.28 150.59,2948.62 150.59,3027.36 327.76,3027.36 327.76,3263.58
no net on AUX Route Horz "AUX Horz" (solid, pour order 14): 1061.02,3263.58 1061.02,3019.88 1155.51,3019.88 1155.51,3263.58 1762.8,3263.58 1762.8,3027.36 1939.96,3027.36 1939.96,2948.62 1931.3,2957.28 1861.22,2957.28 1861.22,2721.06 2060.24,2522.05 2060.24,768.11 1861.22,569.09 1861.22,332.87 1931.3,332.87 1939.96,341.54 1939.96,262.8 1762.8,262.8 1762.8,26.57 1154.53,26.57 1154.53,271.85 1060.04,271.85 1060.04,26.57 327.76,26.57 327.76,262.8 150.59,262.8 150.59,341.54 159.25,332.87 229.33,332.87 229.33,569.09 27.56,770.87 27.56,2519.29 229.33,2721.06 229.33,2957.28 159.25,2957.28 150.59,2948.62 150.59,3027.36 327.76,3027.36 327.76,3263.58
no net on AUX Route Horz "AUX Route Horz-No Net" (solid, pour order 33): 463,181
Vped1 on AUX Route Horz "VPED1_L06_P023" (solid, remove dead copper, pour order 23): 350,439 350,714 1795,714 1802,707 1802,382.29 350,371.29 350,437
no net on GND (split plane): 1742.7,3027.36 1743.08,3023.44 1744.23,3019.67 1746.09,3016.2 1748.58,3013.15 1751.63,3010.65 1755.1,3008.8 1758.87,3007.65 1762.8,3007.27 1919.86,3007.27 1919.86,2977.38 1861.22,2977.38 1857.3,2976.99 1853.53,2975.85 1850.06,2973.99 1847.01,2971.49 1844.51,2968.45 1842.65,2964.97 1841.51,2961.2 1841.12,2957.28 1841.12,2721.06 1841.51,2717.14 1842.65,2713.37 1844.51,2709.9 1847.01,2706.85 2040.14,2513.72 2040.14,776.43 1847.01,583.31 1844.51,580.26 1842.65,576.79 1841.51,573.02 1841.12,569.09 1841.12,332.87 1841.51,328.95 1842.65,325.18 1844.51,321.71 1847.01,318.66 1850.06,316.16 1853.53,314.31 1857.3,313.16 1861.22,312.78 1919.86,312.78 1919.86,282.89 1762.8,282.89 1758.87,282.51 1755.1,281.36 1751.63,279.51 1748.58,277.01 1746.09,273.96 1744.23,270.49 1743.08,266.72 1742.7,262.8 1742.7,46.67 1174.62,46.67 1174.62,271.85 1174.24,275.77 1173.09,279.54 1171.24,283.02 1168.74,286.06 1165.69,288.56 1162.22,290.42 1158.45,291.56 1154.53,291.95 1060.04,291.95 1056.12,291.56 1052.35,290.42 1048.87,288.56 1045.83,286.06 1043.33,283.02 1041.47,279.54 1040.33,275.77 1039.94,271.85 1039.94,46.67 347.85,46.67 347.85,262.8 347.47,266.72 346.32,270.49 344.47,273.96 341.97,277.01 338.92,279.51 335.45,281.36 331.68,282.51 327.76,282.89 170.69,282.89 170.69,312.78 229.33,312.78 233.25,313.16 237.02,314.31 240.5,316.16 243.54,318.66 246.04,321.71 247.9,325.18 249.04,328.95 249.43,332.87 249.43,569.09 249.04,573.02 247.9,576.79 246.04,580.26 243.54,583.31 47.66,779.19 47.66,2510.97 243.54,2706.85 246.04,2709.9 247.9,2713.37 249.04,2717.14 249.43,2721.06 249.43,2957.28 249.04,2961.2 247.9,2964.97 246.04,2968.45 243.54,2971.49 240.5,2973.99 237.02,2975.85 233.25,2976.99 229.33,2977.38 170.69,2977.38 170.69,3007.27 327.76,3007.27 331.68,3007.65 335.45,3008.8 338.92,3010.65 341.97,3013.15 344.47,3016.2 346.32,3019.67 347.47,3023.44 347.85,3027.36 347.85,3243.49 1040.93,3243.49 1040.93,3019.88 1041.31,3015.96 1042.46,3012.19 1044.31,3008.72 1046.81,3005.67 1049.86,3003.17 1053.33,3001.31 1057.1,3000.17 1061.02,2999.79 1155.51,2999.79 1159.43,3000.17 1163.2,3001.31 1166.68,3003.17 1169.72,3005.67 1172.22,3008.72 1174.08,3012.19 1175.22,3015.96 1175.61,3019.88 1175.61,3243.49 1742.7,3243.49
no net on GND (Plane2) (split plane): 1742.7,3027.36 1743.08,3023.44 1744.23,3019.67 1746.09,3016.2 1748.58,3013.15 1751.63,3010.65 1755.1,3008.8 1758.87,3007.65 1762.8,3007.27 1919.86,3007.27 1919.86,2977.38 1861.22,2977.38 1857.3,2976.99 1853.53,2975.85 1850.06,2973.99 1847.01,2971.49 1844.51,2968.45 1842.65,2964.97 1841.51,2961.2 1841.12,2957.28 1841.12,2721.06 1841.51,2717.14 1842.65,2713.37 1844.51,2709.9 1847.01,2706.85 2040.14,2513.72 2040.14,776.43 1847.01,583.31 1844.51,580.26 1842.65,576.79 1841.51,573.02 1841.12,569.09 1841.12,332.87 1841.51,328.95 1842.65,325.18 1844.51,321.71 1847.01,318.66 1850.06,316.16 1853.53,314.31 1857.3,313.16 1861.22,312.78 1919.86,312.78 1919.86,282.89 1762.8,282.89 1758.87,282.51 1755.1,281.36 1751.63,279.51 1748.58,277.01 1746.09,273.96 1744.23,270.49 1743.08,266.72 1742.7,262.8 1742.7,46.67 1174.62,46.67 1174.62,271.85 1174.24,275.77 1173.09,279.54 1171.24,283.02 1168.74,286.06 1165.69,288.56 1162.22,290.42 1158.45,291.56 1154.53,291.95 1060.04,291.95 1056.12,291.56 1052.35,290.42 1048.87,288.56 1045.83,286.06 1043.33,283.02 1041.47,279.54 1040.33,275.77 1039.94,271.85 1039.94,46.67 347.85,46.67 347.85,262.8 347.47,266.72 346.32,270.49 344.47,273.96 341.97,277.01 338.92,279.51 335.45,281.36 331.68,282.51 327.76,282.89 170.69,282.89 170.69,312.78 229.33,312.78 233.25,313.16 237.02,314.31 240.5,316.16 243.54,318.66 246.04,321.71 247.9,325.18 249.04,328.95 249.43,332.87 249.43,569.09 249.04,573.02 247.9,576.79 246.04,580.26 243.54,583.31 47.66,779.19 47.66,2510.97 243.54,2706.85 246.04,2709.9 247.9,2713.37 249.04,2717.14 249.43,2721.06 249.43,2957.28 249.04,2961.2 247.9,2964.97 246.04,2968.45 243.54,2971.49 240.5,2973.99 237.02,2975.85 233.25,2976.99 229.33,2977.38 170.69,2977.38 170.69,3007.27 327.76,3007.27 331.68,3007.65 335.45,3008.8 338.92,3010.65 341.97,3013.15 344.47,3016.2 346.32,3019.67 347.47,3023.44 347.85,3027.36 347.85,3243.49 1040.93,3243.49 1040.93,3019.88 1041.31,3015.96 1042.46,3012.19 1044.31,3008.72 1046.81,3005.67 1049.86,3003.17 1053.33,3001.31 1057.1,3000.17 1061.02,2999.79 1155.51,2999.79 1159.43,3000.17 1163.2,3001.31 1166.68,3003.17 1169.72,3005.67 1172.22,3008.72 1174.08,3012.19 1175.22,3015.96 1175.61,3019.88 1175.61,3243.49 1742.7,3243.49
no net on 2.5V (split plane): 1742.7,3027.36 1743.08,3023.44 1744.23,3019.67 1746.09,3016.2 1748.58,3013.15 1751.63,3010.65 1755.1,3008.8 1758.87,3007.65 1762.8,3007.27 1919.86,3007.27 1919.86,2977.38 1861.22,2977.38 1857.3,2976.99 1853.53,2975.85 1850.06,2973.99 1847.01,2971.49 1844.51,2968.45 1842.65,2964.97 1841.51,2961.2 1841.12,2957.28 1841.12,2721.06 1841.51,2717.14 1842.65,2713.37 1844.51,2709.9 1847.01,2706.85 2040.14,2513.72 2040.14,776.43 1847.01,583.31 1844.51,580.26 1842.65,576.79 1841.51,573.02 1841.12,569.09 1841.12,332.87 1841.51,328.95 1842.65,325.18 1844.51,321.71 1847.01,318.66 1850.06,316.16 1853.53,314.31 1857.3,313.16 1861.22,312.78 1919.86,312.78 1919.86,282.89 1762.8,282.89 1758.87,282.51 1755.1,281.36 1751.63,279.51 1748.58,277.01 1746.09,273.96 1744.23,270.49 1743.08,266.72 1742.7,262.8 1742.7,46.67 1174.62,46.67 1174.62,271.85 1174.24,275.77 1173.09,279.54 1171.24,283.02 1168.74,286.06 1165.69,288.56 1162.22,290.42 1158.45,291.56 1154.53,291.95 1060.04,291.95 1056.12,291.56 1052.35,290.42 1048.87,288.56 1045.83,286.06 1043.33,283.02 1041.47,279.54 1040.33,275.77 1039.94,271.85 1039.94,46.67 347.85,46.67 347.85,262.8 347.47,266.72 346.32,270.49 344.47,273.96 341.97,277.01 338.92,279.51 335.45,281.36 331.68,282.51 327.76,282.89 170.69,282.89 170.69,312.78 229.33,312.78 233.25,313.16 237.02,314.31 240.5,316.16 243.54,318.66 246.04,321.71 247.9,325.18 249.04,328.95 249.43,332.87 249.43,569.09 249.04,573.02 247.9,576.79 246.04,580.26 243.54,583.31 47.66,779.19 47.66,2510.97 243.54,2706.85 246.04,2709.9 247.9,2713.37 249.04,2717.14 249.43,2721.06 249.43,2957.28 249.04,2961.2 247.9,2964.97 246.04,2968.45 243.54,2971.49 240.5,2973.99 237.02,2975.85 233.25,2976.99 229.33,2977.38 170.69,2977.38 170.69,3007.27 327.76,3007.27 331.68,3007.65 335.45,3008.8 338.92,3010.65 341.97,3013.15 344.47,3016.2 346.32,3019.67 347.47,3023.44 347.85,3027.36 347.85,3243.49 1040.93,3243.49 1040.93,3019.88 1041.31,3015.96 1042.46,3012.19 1044.31,3008.72 1046.81,3005.67 1049.86,3003.17 1053.33,3001.31 1057.1,3000.17 1061.02,2999.79 1155.51,2999.79 1159.43,3000.17 1163.2,3001.31 1166.68,3003.17 1169.72,3005.67 1172.22,3008.72 1174.08,3012.19 1175.22,3015.96 1175.61,3019.88 1175.61,3243.49 1742.7,3243.49

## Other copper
Multi-Layer:
  circle w10: c185.04,2913.39 r39.38
  circle w10: c1907.68,2913.58 r39.38
  circle w10: c1905.12,377.56 r39.38
  circle w10: c185.83,377.56 r39.38

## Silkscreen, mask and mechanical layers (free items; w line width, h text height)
Top Overlay:
  drawing of 160 lines, arcs and shapes, not listed
  text "IDL" at 2218.78,312.93 h50
  text "Instrumental" at 2218.78,262.93 h25
  text "Development" at 2218.78,222.93 h25
  text "Lab" at 2218.78,182.93 h25
  text "ModRICH Daughtercard" at 2216.78,116.93 h25
  text "IDL_18_011, 2018-03" at 2218.18,71.13 h25
  text "TL" at 2217.88,19.93 h25
Mechanical 2:
  lines w10: 52.17,2855.12 2120.67,2855.12 ; 52.17,2855.12 2120.67,2855.12 ; 52.17,2855.12 2120.67,2855.12
  text "University of Hawaii at Manoa" at 11726.8,-730.16 h100
  text "High Energy Physics Group" at 11726.8,-828.59 h100
  text "Instrumentation Development Laboratory" at 11726.8,-930.95 h100
Mechanical 3:
  text "University of Hawaii at Manoa" at -190,-740 h100
  text "High Energy Physics Group" at -198.31,-832.53 h100
  text "Instrumentation Development Laboratory" at -198.31,-934.89 h100
Drill Drawing:
  text "Notes:" at 7708.6,9040.93 h130
  text "1. Board shall be fabricated - performace class II as per IPC-6011 and IPC6012" at 7708.6,8915.93 h100
  text "2. PCB manufacturer logo, P/N, revision and/or date code of manufacturing" at 7708.6,8790.93 h100
  text "shall be printed in top solder mask (not over pcb traces, allowed over copper plane)." at 7808.6,8690.93 h100
  text "The date code shall be in the format: \"WWYY\" where WW=week and YY= year, max height 0.15 inches" at 7808.6,8590.93 h100
  text "3. Silkscreen not printed on both sides" at 7708.6,8465.93 h100
  text "4. Material: high temperature FR4 class epoxy glass rated UL94V-0. UL symbol and rating shall be marked farside" at 7708.6,8340.93 h100
  text "35um copper for external layers and 18um for all internal layers" at 7808.62,8240.93 h100
  text "Must be RoHS compliant and survive a lead-free assembly max reflow of 260 deg C (5 passes)" at 7808.6,8140.93 h100
  text "Td rating: >340 deg C" at 7858.6,8015.93 h100
  text "Tg = 150 deg C (min)" at 7862.63,7905.67 h100
  text "5. Solder mask: SMOBC per IPC-SM-840C, class T must be Rohs compliant, 0.001\" max measured over bare copper plating," at 7708.6,7665.93 h100
  text "must clear all lands as indicated on gerber solder mask layers, color= GREEN" at 7808.6,7565.93 h100
  text "6. Finish: electro-less nickel immersion gold (ENIG), 0.05-0.125um Au over 3-6um Ni - over bare copper only" at 7708.39,7412.11 h100
  text "7. Solderability test: Category 2 of J-STD-003" at 7708.6,7265.93 h100
  text "8. Finished boards shall not have nicks, scratches, voids, exposed copper, poor plating or misdrilled holes" at 7708.6,7115.93 h100
  text "9. All holes sizes are after plating" at 7708.6,6965.93 h100
  text "10. PCB manufacturer may add copper thieving as needed to improve manufacturability," at 7658.6,6815.93 h100
  text "thieving to be 0.030\" round pads at 0.050\" spacing." at 7808.6,6715.93 h100
  text "Thieving will have a minimum of 0.100\" clearance from existing copper and should not be placed under surface mounted devices" at 7808.6,6615.93 h100
  text "11. PCB manufacturer may use tear drops to improve annular rings as long as DRC rules are followed" at 7663.6,6475.93 h100
  text "12. All via connections to power and ground planes are solid" at 7663.6,6335.93 h100
  text "13. All unconnected pads on inner signal layers are removed" at 7663.6,6195.93 h100
  text "14. All finished boards are to be 100% electrically tested" at 7663.62,6055.93 h100
  text "15. Unless otherwise indicated, all linear toleracnes shall be XX.X +/-0.2mm and XX.XX +/- 0.1mm" at 7663.6,5915.93 h100
  text "16. Gerber file GM1 shows board outline (milling line)" at 7663.59,5775.91 h100
  text "17. Table 1 shows Layer stack details" at 7663.58,5635.9 h100
  text "Additional notes:" at 7668.6,5370.93 h130
  text "A1. Finished board thickness = 1.27mm +/- 0.1mm; measured over top/bottom copper and solder mask" at 7668.62,5230.93 h100
  text "Table 1a: Layer Stack Details for IDL_14_35 Rev.B (Imperial Units)" at 7652,4470.63 h98.43
  text "Table 2: NC Drill Details for IDL_14_35 Rev.B" at 4892,2161.49 h98.43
